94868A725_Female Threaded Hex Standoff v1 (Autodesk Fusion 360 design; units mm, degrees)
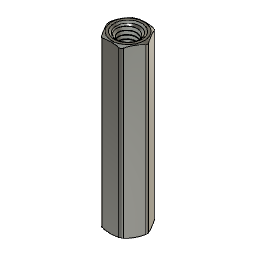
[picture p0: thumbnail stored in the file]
description: STEP AP203
part number: 94868A725_Female Threaded Hex Standoff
